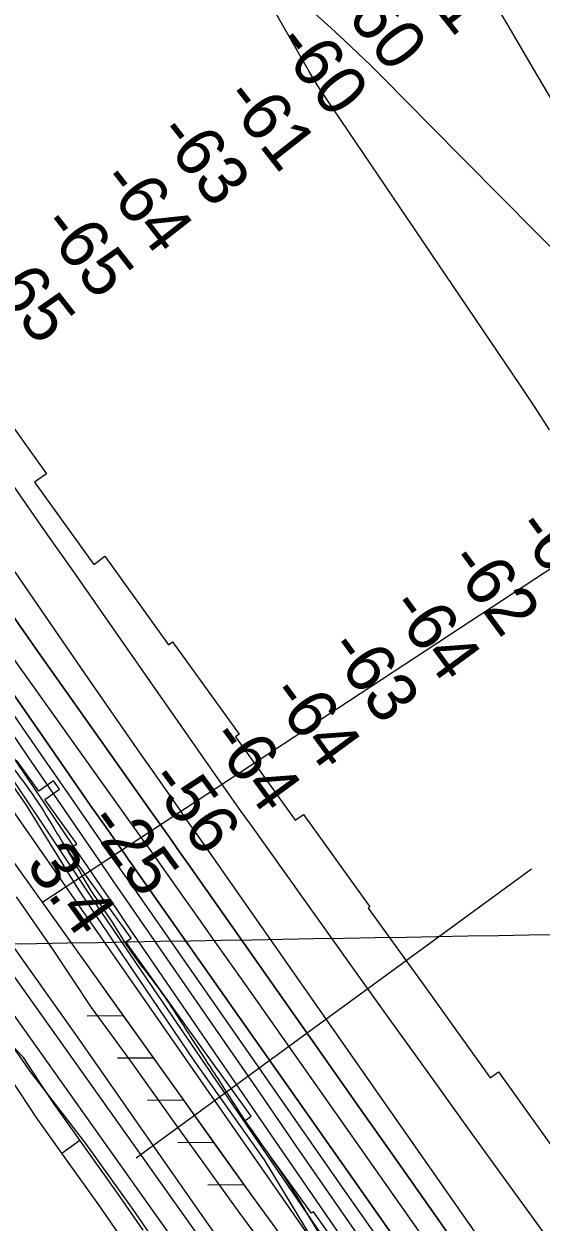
# Model space of a CAD drawing. Extents: x 3892998 to 3931244, y 278583 to 304547.
# Drawn here: x 3910137 to 3910834, y 289921 to 291536 of the extents above; entities that cross this region are included whole.
import ezdxf

# ---------------------------------------------------------------- set-up
doc = ezdxf.new("R2010")
doc.units = 0
for name, color, linetype in [('V-GRID-MAJR', 7, 'Continuous'), ('V-LEVE-TOET', 7, 'Continuous'), ('V-RIVR-EDGE', 7, 'Continuous'), ('V-RIVR-RANG', 7, 'Continuous'), ('V-ROAD-CNTR', 7, 'Continuous'), ('V-RRAP-FSHR', 7, 'Continuous'), ('V-RRAP-RVMT', 7, 'Continuous'), ('V-SITE-VEGE', 7, 'Continuous'), ('V-SURV-LINE', 7, 'Continuous'), ('V-TOPO-DPTH', 7, 'Continuous'), ('V-TOPO-MAJR', 7, 'Continuous'), ('V-TOPO-MINR', 7, 'Continuous'), ('V-TOPO-WATR', 7, 'Continuous'), ('V-UTIL-LINE', 7, 'Continuous')]:
    doc.layers.add(name, color=color, linetype=linetype)

msp = doc.modelspace()

# ---------------------------------------------------------------- linework, layer by layer
at = {"layer": 'V-GRID-MAJR'}
msp.add_spline([(3897162.9, 290075.2), (3902475.5, 290165.2), (3907788.2, 290256), (3913100.9, 290347.6), (3918413.5, 290440), (3923726.1, 290533.1), (3929038.7, 290627)], degree=3, dxfattribs=at)
at = {"layer": 'V-LEVE-TOET'}
for points in [[(3910116.7, 290300.7), (3910209, 290170.6), (3910294.5, 290047.8), (3910382.9, 289921.1), (3910461.3, 289811.8)], [(3910378.5, 289800.4), (3910286.7, 289934.9), (3910220.6, 290027.2), (3910146.3, 290123.1), (3910063.6, 290241.1)]]:
    msp.add_lwpolyline(points, dxfattribs=at)
at = {"layer": 'V-RIVR-EDGE'}
msp.add_spline([(3909865.8, 290928.2), (3909862.6, 290923.1), (3909860.7, 290922.6), (3909860.7, 290920.7), (3909870.3, 290905.1), (3909881.9, 290877.9), (3909893.5, 290856.5), (3909906.1, 290843.8), (3909921.6, 290817.6), (3909937.1, 290794.7), (3909948.2, 290777.2), (3909977.7, 290734.4), (3910003.4, 290694.5), (3910040.6, 290645.9), (3910078.4, 290595.3), (3910114.2, 290544.2), (3910151.5, 290493.6), (3910182, 290444.5), (3910200.8, 290413.3), (3910226.9, 290368.6), (3910256.9, 290323.8), (3910278.7, 290289.3), (3910307.7, 290250.4), (3910325.2, 290226.5), (3910363.9, 290167.2), (3910391.4, 290124.9), (3910427.7, 290068.9), (3910449.5, 290036.8), (3910504.2, 289956.6), (3910522.1, 289926.9), (3910550.1, 289879.7), (3910562.2, 289857.4), (3910573.3, 289842.3), (3910610.6, 289806.7), (3910620.8, 289794.1), (3910623.2, 289780), (3910634.8, 289764.4), (3910664.8, 289724), (3910692.4, 289689.5), (3910710.8, 289668.1), (3910721, 289660.3), (3910770.9, 289605.3), (3910782.5, 289588.7), (3910807.7, 289548.4), (3910835.7, 289503.6), (3910862.8, 289470), (3910892.3, 289425.8), (3910920.4, 289383.5), (3910948, 289342.6), (3910968.8, 289304.7), (3911000.2, 289260.9), (3911019.6, 289231.7), (3911055.9, 289191.3), (3911085.5, 289159.7), (3911118.9, 289116.8), (3911139.2, 289091.1), (3911161, 289062.3), (3911184.2, 289025.9), (3911223.4, 288981.6), (3911281.5, 288916.4), (3911313, 288876.9), (3911328.5, 288859.4), (3911346.4, 288837.5), (3911371.6, 288801), (3911404.5, 288751.9), (3911426.7, 288715.4), (3911446.6, 288687.7), (3911479, 288646.8), (3911529.4, 288582.1), (3911550.6, 288552.9), (3911609.2, 288468.3), (3911644.5, 288421.1), (3911677, 288378.8), (3911701.2, 288348.1), (3911741.4, 288303.8), (3911770.9, 288264.9), (3911788.8, 288235.7), (3911834.3, 288164.7), (3911857.5, 288130.2), (3911884.6, 288092.7), (3911915.6, 288045.5), (3911921.9, 288035.8), (3911928.6, 288029.9), (3911972.6, 287945.8), (3911992.9, 287906.4), (3912000.6, 287887), (3912014.7, 287866.5), (3912026.8, 287848.1), (3912066.4, 287785.3), (3912084.8, 287750.8), (3912094.5, 287732.8), (3912094.9, 287726), (3912096.8, 287711.4), (3912096.3, 287704.6), (3912095.4, 287700.3), (3912088.6, 287695.9), (3912085.6, 287696.9), (3912073, 287702.3), (3912062.4, 287706.2), (3912054.1, 287706.2), (3912051.2, 287704.3), (3912049.2, 287697.9), (3912054, 287685.8), (3912068.6, 287663.9), (3912113.1, 287586.6), (3912136.7, 287540.9), (3912153.7, 287513.6), (3912163.8, 287503.9), (3912187.6, 287479.6), (3912207.4, 287453.3), (3912216.1, 287446), (3912226.8, 287436.2), (3912240.8, 287416.8), (3912253.4, 287397.8), (3912271.3, 287366.2), (3912283.9, 287341.4), (3912284.8, 287339), (3912290.2, 287338), (3912303.8, 287344.3), (3912317.4, 287350.5), (3912319.8, 287350.5), (3912322.7, 287350.5), (3912327.6, 287345.7), (3912328.5, 287338.4), (3912335.8, 287321.4), (3912348.4, 287300), (3912369.2, 287275.1), (3912380.3, 287265.4), (3912402.1, 287253.2), (3912416.7, 287243.5), (3912434.2, 287238.1), (3912456.9, 287220), (3912481.6, 287183.6), (3912501.9, 287148.1), (3912512.6, 287124.7), (3912531.4, 287085.8), (3912550.3, 287059.6), (3912569.6, 287034.3), (3912593.3, 286996.8), (3912613.7, 286968.1), (3912632, 286936.5), (3912645.1, 286912.7), (3912660.6, 286888.8), (3912675.1, 286867.4), (3912698.3, 286835.3), (3912720.1, 286784.8), (3912737, 286747.8), (3912742.3, 286740), (3912755.3, 286715.2), (3912761.6, 286696.8), (3912774.1, 286660.3), (3912779.9, 286635.5), (3912793.4, 286585.5), (3912797.2, 286569.4), (3912804, 286543.7), (3912804.4, 286532)], degree=3, dxfattribs=at)
at = {"layer": 'V-RIVR-RANG'}
msp.add_line((3910288.3, 290007.5), (3910820.9, 290397.4), dxfattribs=at)
at = {"layer": 'V-ROAD-CNTR'}
msp.add_line((3910188.2, 290013.9), (3910212.6, 290031.3), dxfattribs=at)
for points in [[(3910297.9, 289910.1), (3910262.3, 289961.6), (3910220.2, 290020.7), (3910178.3, 290079.5), (3910157.8, 290110.4), (3910136.4, 290142.7), (3910125.4, 290154.5), (3910112.3, 290164.6), (3910089.1, 290176.9), (3910065.5, 290180.3), (3910043, 290175.2), (3910027, 290166.8), (3910013.2, 290158.3), (3909976.8, 290134.6), (3909941.4, 290109.3), (3909883, 290061.9), (3909826, 290013.5), (3909794, 289985.5), (3909762.1, 289957.6), (3909734.3, 289933.6), (3909706.6, 289910.3)], [(3910273, 289893.5), (3910237.8, 289944.4), (3910195.8, 290003.3), (3910153.5, 290062.5), (3910132.8, 290093.9), (3910112.8, 290124), (3910105.1, 290132.2), (3910096, 290139.3), (3910079.7, 290147.9), (3910066.7, 290149.8), (3910053.5, 290146.8), (3910041.8, 290140.7), (3910029.2, 290133), (3909993.7, 290109.8), (3909959.6, 290085.4), (3909902.1, 290038.8), (3909845.6, 289990.8), (3909813.8, 289962.9), (3909781.8, 289934.9), (3909753.7, 289910.8)]]:
    msp.add_lwpolyline(points, dxfattribs=at)
at = {"layer": 'V-RRAP-FSHR'}
for p, q in [((3910271.2, 290199.2), (3910222.4, 290198.7)), ((3910311.9, 290142.2), (3910263.1, 290141.8)), ((3910352.6, 290085.2), (3910303.7, 290084.8)), ((3910393.2, 290028.3), (3910344.4, 290027.8)), ((3910433.9, 289971.3), (3910385.1, 289970.8))]:
    msp.add_line(p, q, dxfattribs=at)
for points in [[(3906808.7, 295088), (3907517.5, 294080), (3908118.6, 293281.7), (3908235.5, 293171.3), (3908399.7, 292987.4), (3908497.6, 292843.4), (3908620.8, 292699.4), (3908781.9, 292472.6), (3908840.2, 292361), (3908947.1, 292209.3), (3909156.9, 291945.8), (3909268, 291726.3), (3910057.1, 290568.3), (3910757.5, 289562.2), (3911229.4, 288921.6), (3911814.1, 288135.2), (3912099.8, 287690.4), (3912357.7, 287495.4), (3912493.3, 287323.3)], [(3911412.6, 288622.2), (3911308, 288752.8), (3911327.8, 288790.6), (3910785.8, 289488.4), (3910445.8, 289954.6), (3910129.3, 290398), (3909798.6, 290866.3), (3909546.9, 291228.9), (3909473.8, 291330.5), (3909414.7, 291394.5), (3909312.2, 291557.4), (3909036.8, 291981.1), (3908774.4, 292360.3)], [(3910271.2, 290199.2), (3910240.1, 290242.7)], [(3910311.9, 290142.2), (3910271.2, 290199.2)], [(3910352.6, 290085.2), (3910311.9, 290142.2)], [(3910393.2, 290028.3), (3910352.6, 290085.2)], [(3910433.9, 289971.3), (3910393.2, 290028.3)], [(3910475, 289914.6), (3910445.8, 289954.6), (3910433.9, 289971.3)]]:
    msp.add_lwpolyline(points, dxfattribs=at)
at = {"layer": 'V-RRAP-RVMT'}
for p, q in [((3910082.1, 291048.8), (3910167.5, 290929.9)), ((3910167.5, 290929.9), (3910151.4, 290918.4)), ((3910151.4, 290918.4), (3910231.1, 290807.6)), ((3910231.1, 290807.6), (3910246.2, 290818.5)), ((3910246.2, 290818.5), (3910331.8, 290699.3)), ((3910331.8, 290699.3), (3910337.3, 290703.3)), ((3910337.3, 290703.3), (3910426.9, 290578.6)), ((3910426.9, 290578.6), (3910422, 290575.1)), ((3910422, 290575.1), (3910502.7, 290462.7)), ((3910157, 290502), (3910127.1, 290543.6)), ((3910176.7, 290515.9), (3910157, 290502)), ((3910184.8, 290504.7), (3910176.7, 290515.9)), ((3910165.2, 290490.6), (3910184.8, 290504.7)), ((3910208.2, 290430.8), (3910165.2, 290490.6)), ((3910502.7, 290462.7), (3910513.7, 290470.6)), ((3910513.7, 290470.6), (3910603.3, 290346)), ((3910196.3, 290422.3), (3910208.2, 290430.8)), ((3910281.5, 290303.7), (3910196.3, 290422.3)), ((3910603.3, 290346), (3910601.1, 290344.4)), ((3910601.1, 290344.4), (3910685.3, 290227.3)), ((3910274.5, 290298.7), (3910281.5, 290303.7)), ((3910358.6, 290181.6), (3910274.5, 290298.7)), ((3910685.3, 290227.3), (3910765.4, 290115.6)), ((3910443.3, 290063.7), (3910358.6, 290181.6)), ((3910765.4, 290115.6), (3910776.5, 290123.6)), ((3910776.5, 290123.6), (3910866.1, 289998.8)), ((3910434.9, 290057.7), (3910443.3, 290063.7)), ((3910524.4, 289933.1), (3910434.9, 290057.7)), ((3910527.1, 289935), (3910524.4, 289933.1)), ((3910608.8, 289821.2), (3910527.1, 289935))]:
    msp.add_line(p, q, dxfattribs=at)
at = {"layer": 'V-SITE-VEGE'}
for points in [[(3910073, 290578.5), (3910139.3, 290484.4), (3910210.8, 290369)], [(3910210.8, 290369), (3910280.2, 290265.4), (3910366.8, 290137.5), (3910460.7, 290005.1), (3910525.6, 289897.9), (3910554.1, 289850), (3910565.5, 289833.1), (3910581.6, 289812.7), (3910586.8, 289806.7)], [(3910464.2, 289883.8), (3910422.3, 289941), (3910372.9, 290010), (3910339.8, 290055.1), (3910282.3, 290136.2), (3910228.2, 290210.5), (3910177, 290287.6), (3910126.9, 290359.7)]]:
    msp.add_lwpolyline(points, dxfattribs=at)
at = {"layer": 'V-SURV-LINE'}
for points in [[(3909350, 291341.4), (3910746.5, 289374.8)], [(3910722, 289357.4), (3909325.5, 291324)]]:
    msp.add_lwpolyline(points, dxfattribs=at)
at = {"layer": 'V-TOPO-DPTH'}
for points in [[(3910735.4, 289759.4), (3910292.5, 290389), (3910287.9, 290395.6), (3910283.3, 290402.3), (3910278.6, 290408.9), (3910274, 290415.5), (3910246.9, 290454.1), (3910228.7, 290480), (3910210.6, 290506), (3910192.5, 290531.9), (3910174.5, 290558), (3909911.6, 290937.5), (3909904.2, 290948.4), (3909896.8, 290959.2), (3909889.4, 290970.1), (3909882.1, 290981.1), (3909801.3, 291102.4), (3909753.7, 291174), (3909706.1, 291245.7), (3909658.5, 291317.3), (3909611, 291389), (3909423.1, 291672.5)], [(3910735.4, 289759.4), (3910292.5, 290389), (3910287.9, 290395.6), (3910283.3, 290402.3), (3910278.6, 290408.9), (3910274, 290415.5), (3910246.9, 290454.1), (3910228.7, 290480), (3910210.6, 290506), (3910192.5, 290531.9), (3910174.5, 290558), (3909911.6, 290937.5), (3909904.2, 290948.4), (3909896.8, 290959.2), (3909889.4, 290970.1), (3909882.1, 290981.1), (3909801.3, 291102.4), (3909753.7, 291174), (3909706.1, 291245.7), (3909658.5, 291317.3), (3909611, 291389), (3909423.1, 291672.5)], [(3910052.1, 290779.2), (3910299.7, 290432.8), (3910304.1, 290426.7), (3910308.4, 290420.6), (3910312.8, 290414.5), (3910317.1, 290408.4), (3910350.4, 290361.3), (3910371.3, 290331.6), (3910392.3, 290302), (3910413.2, 290272.3), (3910434.1, 290242.6), (3910726.9, 289826.5)], [(3910052.1, 290779.2), (3910299.7, 290432.8), (3910304.1, 290426.7), (3910308.4, 290420.6), (3910312.8, 290414.5), (3910317.1, 290408.4), (3910350.4, 290361.3), (3910371.3, 290331.6), (3910392.3, 290302), (3910413.2, 290272.3), (3910434.1, 290242.6), (3910726.9, 289826.5)], [(3910769.6, 289818.8), (3910687.9, 289935), (3910636, 290008.9), (3910584.1, 290082.7), (3910532.2, 290156.6), (3910480.2, 290230.4), (3910360, 290401.2), (3910346.8, 290420.1), (3910333.5, 290438.9), (3910320.2, 290457.7), (3910306.9, 290476.6), (3910153.7, 290693.4), (3910118.3, 290743.7)], [(3910769.6, 289818.8), (3910687.9, 289935), (3910636, 290008.9), (3910584.1, 290082.7), (3910532.2, 290156.6), (3910480.2, 290230.4), (3910360, 290401.2), (3910346.8, 290420.1), (3910333.5, 290438.9), (3910320.2, 290457.7), (3910306.9, 290476.6), (3910153.7, 290693.4), (3910118.3, 290743.7)], [(3910096.8, 290614.7), (3910141.5, 290549.4), (3910227.9, 290423.5), (3910242, 290403), (3910256.1, 290382.4), (3910270.2, 290361.9), (3910284.4, 290341.4), (3910403.3, 290169.3), (3910453.9, 290096), (3910504.6, 290022.7), (3910555.3, 289949.4), (3910606, 289876.2)]]:
    msp.add_lwpolyline(points, dxfattribs=at)
at = {"layer": 'V-TOPO-MAJR'}
msp.add_lwpolyline([(3909587.3, 291584), (3909645.6, 291497.5), (3909704, 291411), (3909762.7, 291324.8), (3909821.5, 291238.6), (3909954.4, 291044.6), (3909962.9, 291032.2), (3909971.4, 291019.7), (3909980, 291007.3), (3909988.5, 290994.9), (3910219.3, 290660.3), (3910242.6, 290626.6), (3910266, 290592.8), (3910289.4, 290559.1), (3910312.8, 290525.4), (3910347.4, 290475.7), (3910353.6, 290466.9), (3910359.7, 290458), (3910365.9, 290449.2), (3910372.1, 290440.4), (3910751.9, 289897.1)], dxfattribs=at)
at = {"layer": 'V-TOPO-MINR'}
for points in [[(3909408.8, 291675.3), (3909505.5, 291528.9), (3909563, 291441.9), (3909620.5, 291354.8), (3909677.9, 291267.7), (3909735.3, 291180.5), (3909864.7, 290984), (3909875.6, 290967.6), (3909886.5, 290951.2), (3909897.5, 290934.9), (3909908.5, 290918.6), (3910060, 290696.5), (3910094.8, 290645.7), (3910129.6, 290595), (3910164.6, 290544.3), (3910199.7, 290493.7), (3910251.2, 290419.4), (3910260.6, 290405.9), (3910269.9, 290392.5), (3910279.2, 290379.1), (3910288.6, 290365.7), (3910566, 289967.8), (3910592.4, 289930), (3910618.7, 289892.2)], [(3909423.1, 291672.5), (3909611, 291389), (3909658.5, 291317.3), (3909706.1, 291245.7), (3909753.7, 291174), (3909801.3, 291102.4), (3909882.1, 290981.1), (3909889.4, 290970.1), (3909896.8, 290959.2), (3909904.2, 290948.4), (3909911.6, 290937.5), (3910174.5, 290558), (3910192.5, 290531.9), (3910210.6, 290506), (3910228.7, 290480), (3910246.9, 290454.1), (3910274, 290415.5), (3910278.6, 290408.9), (3910283.3, 290402.3), (3910287.9, 290395.6), (3910292.5, 290389), (3910735.4, 289759.4)], [(3910471.5, 291602.3), (3910551, 291530.4), (3910569.2, 291513.7), (3910587.2, 291496.7), (3910604.9, 291479.5), (3910622.4, 291462.1), (3910683.7, 291400.1), (3910731.7, 291351.6), (3910779.8, 291303.1), (3910827.9, 291254.7), (3910876, 291206.2)], [(3909457.8, 291562.8), (3909478.7, 291530.5), (3909499.6, 291498.1), (3909826.5, 290990.8), (3909845.1, 290962.1), (3909863.7, 290933.5), (3909882.5, 290905), (3909901.3, 290876.5), (3909920.5, 290847.4), (3909949.1, 290804.5), (3909977.7, 290761.6), (3910006.5, 290718.8), (3910035.4, 290676.1), (3910203.6, 290427.9), (3910222.7, 290399.9), (3910241.7, 290371.9), (3910260.7, 290344), (3910279.8, 290316), (3910317.9, 290260.3), (3910356.1, 290204.6), (3910394.2, 290148.8), (3910432.5, 290093.1), (3910470.7, 290037.4), (3910655.7, 289768.5)], [(3910845.4, 290988.8), (3910826, 291019), (3910806.2, 291048.9), (3910543.8, 291436.5), (3910538, 291445.3), (3910532.4, 291454.1), (3910526.9, 291463.1), (3910521.6, 291472.2), (3910467.5, 291566.2)], [(3910850, 291431.6), (3910822.6, 291477.8), (3910795.4, 291524), (3910769.4, 291568.4)], [(3909687.1, 291539.8), (3909729.8, 291477.8), (3909772.7, 291415.9), (3909983.3, 291113.4), (3910002.4, 291086), (3910021.5, 291058.6), (3910040.6, 291031.2), (3910059.7, 291003.8), (3910095.2, 290952.9), (3910132.1, 290900.1), (3910169, 290847.2), (3910205.9, 290794.4), (3910242.8, 290741.5), (3910381.8, 290542.3), (3910397.6, 290519.8), (3910413.5, 290497.2), (3910429.4, 290474.7), (3910445.4, 290452.3), (3910579, 290265.3), (3910628.9, 290195.5), (3910679, 290125.8), (3910729.1, 290056.2), (3910779.4, 289986.6), (3910861.7, 289873.1)], [(3910052.1, 290779.2), (3910299.7, 290432.8), (3910304.1, 290426.7), (3910308.4, 290420.6), (3910312.8, 290414.5), (3910317.1, 290408.4), (3910350.4, 290361.3), (3910371.3, 290331.6), (3910392.3, 290302), (3910413.2, 290272.3), (3910434.1, 290242.6), (3910726.9, 289826.5)], [(3910118.3, 290743.7), (3910153.7, 290693.4), (3910306.9, 290476.6), (3910320.2, 290457.7), (3910333.5, 290438.9), (3910346.8, 290420.1), (3910360, 290401.2), (3910480.2, 290230.4), (3910532.2, 290156.6), (3910584.1, 290082.7), (3910636, 290008.9), (3910687.9, 289935), (3910769.6, 289818.8)], [(3910096.8, 290614.7), (3910141.5, 290549.4), (3910227.9, 290423.5), (3910242, 290403), (3910256.1, 290382.4), (3910270.2, 290361.9), (3910284.4, 290341.4), (3910403.3, 290169.3), (3910453.9, 290096), (3910504.6, 290022.7), (3910555.3, 289949.4), (3910606, 289876.2)]]:
    msp.add_lwpolyline(points, dxfattribs=at)
at = {"layer": 'V-TOPO-WATR'}
msp.add_lwpolyline([(3909387.7, 291650.5), (3909824.2, 290965.9), (3909837.7, 290944.9), (3909851.3, 290923.8), (3909864.9, 290902.8), (3909878.5, 290881.9), (3909892.3, 290861), (3909906, 290840.1), (3909919.9, 290819.2), (3909933.7, 290798.4), (3910196.3, 290406), (3910211.4, 290383.4), (3910226.5, 290360.9), (3910241.7, 290338.4), (3910256.9, 290315.9), (3910272.1, 290293.4), (3910287.3, 290270.9), (3910302.6, 290248.5), (3910317.9, 290226.1), (3910637.4, 289758.5)], dxfattribs=at)
at = {"layer": 'V-UTIL-LINE'}
msp.add_line((3912938.6, 292175.7), (3910162.6, 290352.3), dxfattribs=at)

# ---------------------------------------------------------------- texts
at = {"layer": 'V-RIVR-RANG'}
for s, rotation, p in [('-61', 308.0484, (3910640.4, 291619.8)), ('-60', 308.0484, (3910552.4, 291570)), ('-60', 308.0484, (3910473.5, 291508.5)), ('-61', 308.0484, (3910403.7, 291435.4)), ('-63', 308.0484, (3910314.2, 291387.5)), ('-64', 308.0484, (3910237.4, 291323.4)), ('-65', 308.0484, (3910157.4, 291263.4)), ('-65', 308.0484, (3910078.5, 291201.9)), ('-61', 306.2409, (3910796.8, 290856.3)), ('-62', 306.2409, (3910706.2, 290810.8)), ('-64', 306.2409, (3910627.1, 290749.5)), ('-63', 306.2409, (3910544.3, 290693.4)), ('-64', 306.2409, (3910465.5, 290631.7)), ('-64', 306.2409, (3910384.7, 290572.8)), ('-56', 306.2409, (3910302.5, 290515.8)), ('-25', 305.9583, (3910220.4, 290459.4)), ('3.4', 305.9583, (3910138.2, 290402.4))]:
    msp.add_text(s, height=67, rotation=rotation, dxfattribs=at).set_placement(p)

doc.saveas('drawing.dxf')
